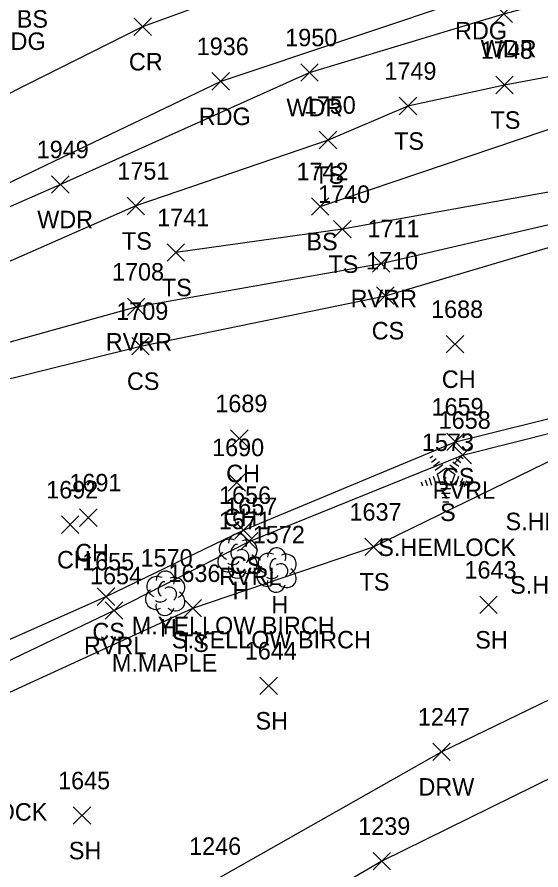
# Model space of a CAD drawing. Extents: x 1621633 to 1624015, y 417863 to 420979.
# Drawn here: x 1621766.2 to 1621826, y 417953.8 to 418051.2 of the extents above; entities that cross this region are included whole.
import ezdxf

# ---------------------------------------------------------------- set-up
doc = ezdxf.new("R2010")
doc.units = 0
for name, color, linetype in [('L_A', 7, 'Continuous'), ('L_C', 7, 'Continuous'), ('L_I', 7, 'Continuous'), ('L_TIC', 7, 'Continuous'), ('LAWA', 7, 'Continuous'), ('LAWE', 7, 'Continuous'), ('LELB', 7, 'Continuous'), ('LTC', 7, 'Continuous'), ('LTD', 7, 'Continuous'), ('P_A', 7, 'Continuous'), ('P_I', 7, 'Continuous'), ('P_TIC', 7, 'Continuous'), ('PEU', 7, 'Continuous'), ('PRC', 7, 'Continuous'), ('R_A', 7, 'Continuous'), ('R_I', 7, 'Continuous'), ('R_TIC', 7, 'Continuous'), ('RDW', 7, 'Continuous')]:
    doc.layers.add(name, color=color, linetype=linetype)

msp = doc.modelspace()

# ---------------------------------------------------------------- linework, layer by layer
at = {"layer": 'L_TIC'}
for points in [[(1621820.796, 418050.595), (1621822.796, 418052.595)], [(1621822.796, 418050.595), (1621820.796, 418052.595)], [(1621798.594, 418043.877), (1621800.594, 418045.877)], [(1621800.594, 418043.877), (1621798.594, 418045.877)], [(1621820.87, 418042.443), (1621822.87, 418044.443)], [(1621822.87, 418042.443), (1621820.87, 418044.443)], [(1621809.848, 418040.046), (1621811.848, 418042.046)], [(1621811.848, 418040.046), (1621809.848, 418042.046)], [(1621800.708, 418036.161), (1621802.708, 418038.161)], [(1621802.708, 418036.161), (1621800.708, 418038.161)], [(1621770.105, 418031.081), (1621772.105, 418033.081)], [(1621772.105, 418031.081), (1621770.105, 418033.081)], [(1621778.745, 418028.631), (1621780.745, 418030.631)], [(1621780.745, 418028.631), (1621778.745, 418030.631)], [(1621799.802, 418028.566), (1621801.802, 418030.566)], [(1621801.802, 418028.566), (1621799.802, 418030.566)], [(1621802.346, 418025.98), (1621804.346, 418027.98)], [(1621804.346, 418025.98), (1621802.346, 418027.98)], [(1621783.312, 418023.309), (1621785.312, 418025.309)], [(1621785.312, 418023.309), (1621783.312, 418025.309)], [(1621806.782, 418022.044), (1621808.782, 418024.044)], [(1621808.782, 418022.044), (1621806.782, 418024.044)], [(1621807.258, 418018.376), (1621809.258, 418020.376)], [(1621809.258, 418018.376), (1621807.258, 418020.376)], [(1621778.786, 418017.1), (1621780.786, 418019.1)], [(1621780.786, 418017.1), (1621778.786, 418019.1)], [(1621779.28, 418012.608), (1621781.28, 418014.608)], [(1621781.28, 418012.608), (1621779.28, 418014.608)], [(1621815.223, 418012.832), (1621817.223, 418014.832)], [(1621817.223, 418012.832), (1621815.223, 418014.832)], [(1621790.571, 418002.06), (1621792.571, 418004.06)], [(1621792.571, 418002.06), (1621790.571, 418004.06)], [(1621815.284, 418001.68), (1621817.284, 418003.68)], [(1621817.284, 418001.68), (1621815.284, 418003.68)], [(1621816.095, 418000.163), (1621818.095, 418002.163)], [(1621818.095, 418000.163), (1621816.095, 418002.163)], [(1621790.283, 417997.037), (1621792.283, 417999.037)], [(1621792.283, 417997.037), (1621790.283, 417999.037)], [(1621773.311, 417993.012), (1621775.311, 417995.012)], [(1621775.311, 417993.012), (1621773.311, 417995.012)], [(1621771.238, 417992.206), (1621773.238, 417994.206)], [(1621773.238, 417992.206), (1621771.238, 417994.206)], [(1621791.046, 417991.579), (1621793.046, 417993.579)], [(1621793.046, 417991.579), (1621791.046, 417993.579)], [(1621791.696, 417990.301), (1621793.696, 417992.301)], [(1621793.696, 417990.301), (1621791.696, 417992.301)], [(1621805.904, 417989.669), (1621807.904, 417991.669)], [(1621807.904, 417989.669), (1621805.904, 417991.669)], [(1621775.332, 417983.988), (1621777.332, 417985.988)], [(1621777.332, 417983.988), (1621775.332, 417985.988)], [(1621819.048, 417983.049), (1621821.048, 417985.049)], [(1621821.048, 417983.049), (1621819.048, 417985.049)], [(1621776.237, 417982.398), (1621778.237, 417984.398)], [(1621778.237, 417982.398), (1621776.237, 417984.398)], [(1621785.253, 417982.66), (1621787.253, 417984.66)], [(1621787.253, 417982.66), (1621785.253, 417984.66)], [(1621793.931, 417973.797), (1621795.931, 417975.797)], [(1621795.931, 417973.797), (1621793.931, 417975.797)], [(1621772.591, 417958.968), (1621774.591, 417960.968)], [(1621774.591, 417958.968), (1621772.591, 417960.968)]]:
    msp.add_lwpolyline(points, dxfattribs=at)
at = {"layer": 'LAWA'}
msp.add_lwpolyline([(1621679.191, 417971.595), (1621702.483, 417990.446), (1621715.012, 418000.477), (1621736.638, 418013.959), (1621752.876, 418023.199), (1621756.92, 418025.879), (1621771.105, 418032.081), (1621799.594, 418044.877), (1621821.796, 418051.595), (1621846.965, 418058.282), (1621864.113, 418063.689), (1621891.562, 418069.816), (1621913.254, 418074.106), (1621937.152, 418070.696)], dxfattribs=at)
at = {"layer": 'LAWE'}
for points in [[(1621694.469, 417944.857), (1621713.846, 417956.733), (1621742.172, 417966.049), (1621760.532, 417975.456), (1621777.237, 417983.398), (1621792.696, 417991.301), (1621817.095, 418001.163), (1621844.467, 418008.037), (1621871.363, 418013.308), (1621897.422, 418019.495), (1621922.912, 418028.804), (1621945.859, 418038.978), (1621969.359, 418051.535), (1621990.012, 418069.674), (1621996.064, 418084.217), (1621996.533, 418092.287)], [(1621682.822, 417967.998), (1621698.064, 417979.126), (1621716.448, 417990.621), (1621740.687, 418004.296), (1621760.276, 418012.676), (1621779.786, 418018.1), (1621807.782, 418023.044), (1621832.841, 418028.899), (1621852.452, 418034.783), (1621876.37, 418040.125), (1621904.646, 418043.594), (1621931.259, 418052.925), (1621950.617, 418064.927), (1621964.804, 418074.349), (1621971.864, 418081.724)]]:
    msp.add_lwpolyline(points, dxfattribs=at)
at = {"layer": 'LELB'}
for points in [[(1621694.018, 417945.604), (1621713.058, 417958.392), (1621741.418, 417968.002), (1621759.92, 417977.729), (1621776.332, 417984.988), (1621792.046, 417992.579), (1621816.284, 418002.68), (1621844.088, 418009.589), (1621869.849, 418015.692), (1621896.837, 418021.913), (1621921.805, 418030.632), (1621944.897, 418041.057), (1621968.773, 418053.066), (1621989.111, 418070.538), (1621994.262, 418084.512), (1621994.522, 418092.07)], [(1621714.218, 417979.319), (1621742.211, 418002.577), (1621762.579, 418009.214), (1621780.28, 418013.608), (1621808.258, 418019.376), (1621833.473, 418026.83), (1621853.516, 418030.646), (1621878.098, 418035.973), (1621904.446, 418042.094), (1621933.372, 418049.997), (1621951.553, 418063.416), (1621967.003, 418072.955), (1621972.682, 418081.713), (1621977.304, 418089.793)], [(1621962.893, 418084.645), (1621941.499, 418069.284), (1621934.526, 418059.292), (1621911.153, 418049.766), (1621884.836, 418045.66), (1621868.891, 418041.418), (1621850.259, 418038.198), (1621830.712, 418031.899), (1621803.346, 418026.98), (1621784.312, 418024.309)], [(1621870.082, 418049.389), (1621847.864, 418048.319), (1621821.87, 418043.443), (1621810.848, 418041.046), (1621801.708, 418037.161), (1621779.745, 418029.631), (1621758.68, 418020.378), (1621745.692, 418010.927), (1621727.629, 418000.827), (1621708.748, 417989.428), (1621682.341, 417970.694)], [(1621800.802, 418029.566), (1621829.213, 418039.175), (1621852.352, 418044.721), (1621867.236, 418045.074)], [(1621696.619, 417939.068), (1621723.715, 417952.351), (1621743.664, 417962.858), (1621762.067, 417972.573), (1621786.253, 417983.66), (1621806.904, 417990.669), (1621831.079, 418002.462), (1621857.774, 418009.445), (1621874.764, 418010.395)]]:
    msp.add_lwpolyline(points, dxfattribs=at)
at = {"layer": 'LTC'}
for p, q in [((1621813.327, 418000.831), (1621813.682, 418001.089)), ((1621813.537, 418000.366), (1621814.066, 418000.75)), ((1621816.354, 418000.723), (1621816.904, 418000.324)), ((1621816.725, 418001.072), (1621817.145, 418000.767)), ((1621813.746, 417999.9), (1621814.45, 418000.411)), ((1621813.956, 417999.434), (1621814.834, 418000.072)), ((1621814.18, 417998.979), (1621815.192, 417999.714)), ((1621815.192, 417999.714), (1621816.189, 417998.989)), ((1621815.612, 418000.027), (1621816.422, 417999.438)), ((1621815.983, 418000.375), (1621816.662, 417999.881)), ((1621813.27, 417998.544), (1621813.542, 417997.708)), ((1621813.726, 417998.76), (1621814.057, 417997.741)), ((1621814.18, 417998.979), (1621814.567, 417997.786)), ((1621816.189, 417998.989), (1621815.798, 417997.786)), ((1621816.627, 417998.718), (1621816.289, 417997.678)), ((1621812.36, 417998.11), (1621812.512, 417997.642)), ((1621812.815, 417998.327), (1621813.027, 417997.675)), ((1621815.798, 417997.786), (1621814.567, 417997.786)), ((1621817.071, 417998.467), (1621816.784, 417997.583)), ((1621817.516, 417998.217), (1621817.279, 417997.488)), ((1621817.96, 417997.967), (1621817.773, 417997.393)), ((1621815.76, 417997.286), (1621814.615, 417997.286)), ((1621815.676, 417996.786), (1621814.687, 417996.786)), ((1621815.592, 417996.286), (1621814.76, 417996.286)), ((1621815.508, 417995.786), (1621814.833, 417995.786))]:
    msp.add_line(p, q, dxfattribs=at)
at = {"layer": 'LTD'}
for p, q in [((1621791.344, 417989.688), (1621791.344, 417989.688)), ((1621791.344, 417989.688), (1621791.344, 417989.688)), ((1621795.799, 417988.071), (1621795.799, 417988.071)), ((1621795.799, 417988.071), (1621795.799, 417988.071)), ((1621783.065, 417985.418), (1621783.065, 417985.418)), ((1621783.065, 417985.418), (1621783.065, 417985.418))]:
    msp.add_line(p, q, dxfattribs=at)
for centre in [(1621791.391, 417991.122), (1621795.845, 417989.505), (1621783.112, 417986.852)]:
    msp.add_arc(centre, 1.047, 335.52715, 180.95627, dxfattribs=at)
for centre, major_axis, ratio, start_param, end_param in [((1621790.552, 417990.355), (1.21, -0.512), 0.895232, 1.570796, 4.712389), ((1621791.136, 417990.147), (-0.208, -0.792), 0.645439, 3.141593, 6.283185), ((1621792.386, 417990.272), (-1.141, -0.483), 0.949671, 1.570796, 4.712389), ((1621790.261, 417988.98), (0.584, -1.042), 0.959034, 3.141593, 6.283185), ((1621791.844, 417989.522), (-0.5, 0.667), 0.989748, 3.141593, 6.283185), ((1621792.344, 417988.855), (-1.09, 0.792), 0.841452, 1.570796, 4.712389), ((1621795.007, 417988.738), (1.21, -0.512), 0.895232, 1.570796, 4.712389), ((1621796.84, 417988.655), (-1.141, -0.483), 0.949671, 1.570796, 4.712389), ((1621790.886, 417988.938), (-0.625, -0.083), 0.423636, 0, 3.141593), ((1621795.59, 417988.529), (-0.208, -0.792), 0.645439, 3.141593, 6.283185), ((1621796.299, 417987.905), (-0.5, 0.667), 0.989748, 3.141593, 6.283185), ((1621791.344, 417988.188), (0.265, 1.061), 0.942809, 1.570796, 4.712389), ((1621794.715, 417987.363), (0.584, -1.042), 0.959034, 3.141593, 6.283185), ((1621796.799, 417987.238), (-1.09, 0.792), 0.841452, 1.570796, 4.712389), ((1621782.273, 417986.085), (1.21, -0.512), 0.895232, 1.570796, 4.712389), ((1621784.106, 417986.002), (-1.141, -0.483), 0.949671, 1.570796, 4.712389), ((1621795.799, 417986.571), (0.265, 1.061), 0.942809, 1.570796, 4.712389), ((1621795.34, 417987.321), (-0.625, -0.083), 0.423636, 0, 3.141593), ((1621782.856, 417985.876), (-0.208, -0.792), 0.645439, 3.141593, 6.283185), ((1621783.565, 417985.251), (-0.5, 0.667), 0.989748, 3.141593, 6.283185), ((1621781.982, 417984.709), (0.584, -1.042), 0.959034, 3.141593, 6.283185), ((1621784.065, 417984.585), (-1.09, 0.792), 0.841452, 1.570796, 4.712389), ((1621783.065, 417983.918), (0.265, 1.061), 0.942809, 1.570796, 4.712389), ((1621782.607, 417984.668), (-0.625, -0.083), 0.423636, 0, 3.141593)]:
    msp.add_ellipse(centre, major_axis=major_axis, ratio=ratio, start_param=start_param, end_param=end_param, dxfattribs=at)
at = {"layer": 'P_TIC'}
for points in [[(1621779.514, 418049.109), (1621781.514, 418051.109)], [(1621781.514, 418049.109), (1621779.514, 418051.109)], [(1621788.443, 418042.868), (1621790.443, 418044.868)], [(1621790.443, 418042.868), (1621788.443, 418044.868)]]:
    msp.add_lwpolyline(points, dxfattribs=at)
at = {"layer": 'PEU'}
msp.add_lwpolyline([(1621912.204, 418078.592), (1621880.997, 418070.288), (1621848.822, 418062.508), (1621818.735, 418053.659), (1621789.443, 418043.868), (1621760.318, 418029.904), (1621735.432, 418015.464), (1621709.615, 417999.398), (1621686.1, 417982.194), (1621676.517, 417973.897)], dxfattribs=at)
at = {"layer": 'PRC'}
msp.add_lwpolyline([(1621971.067, 418099.341), (1621938.438, 418093.726), (1621906.629, 418086.952), (1621874.869, 418079.941), (1621842.519, 418071.194), (1621811.531, 418061.42), (1621780.514, 418050.109), (1621750.947, 418035.3), (1621723.041, 418018.53), (1621696.18, 418000.53), (1621670.933, 417981.571)], dxfattribs=at)
at = {"layer": 'R_TIC'}
for points in [[(1621813.671, 417966.246), (1621815.671, 417968.246)], [(1621815.671, 417966.246), (1621813.671, 417968.246)], [(1621806.862, 417953.759), (1621808.862, 417955.759)], [(1621808.862, 417953.759), (1621806.862, 417955.759)]]:
    msp.add_lwpolyline(points, dxfattribs=at)
at = {"layer": 'RDW'}
msp.add_lwpolyline([(1621894.363, 417990.232), (1621865.95, 417979.751), (1621835.24, 417968.23), (1621807.862, 417954.759), (1621779.016, 417937.89), (1621749.255, 417923.342), (1621721.772, 417904.02), (1621715.875, 417914.033), (1621734.513, 417925.445), (1621760.095, 417937.756), (1621788.575, 417952.475), (1621814.671, 417967.246), (1621841.022, 417980.019), (1621869.66, 417990.005), (1621898.189, 417999.842)], dxfattribs=at)

# ---------------------------------------------------------------- texts
at = {"layer": 'L_A'}
for s, p in [('BS', (1621766.131, 418050.001)), ('WDR', (1621819.158, 418046.595)), ('WDR', (1621796.956, 418039.877)), ('TS', (1621820.28, 418038.443)), ('TS', (1621809.257, 418036.046)), ('TS', (1621800.118, 418032.161)), ('WDR', (1621768.467, 418027.081)), ('TS', (1621778.154, 418024.631)), ('BS', (1621799.243, 418024.566)), ('TS', (1621801.756, 418021.98)), ('TS', (1621782.722, 418019.309)), ('RVRR', (1621804.294, 418018.044)), ('CS', (1621806.699, 418014.376)), ('RVRR', (1621776.298, 418013.1)), ('CS', (1621778.721, 418008.608)), ('CH', (1621814.712, 418008.832)), ('CH', (1621790.06, 417998.06)), ('CS', (1621814.725, 417997.68)), ('RVRL', (1621813.662, 417996.163)), ('S', (1621814.518, 417993.623)), ('CH', (1621789.771, 417993.037)), ('CH', (1621772.799, 417989.012)), ('CH', (1621770.726, 417988.206)), ('CS', (1621790.486, 417987.579)), ('RVRL', (1621789.263, 417986.301)), ('TS', (1621805.313, 417985.669)), ('H', (1621790.777, 417984.688)), ('H', (1621795.232, 417983.071)), ('CS', (1621774.773, 417979.988)), ('H', (1621782.498, 417980.418)), ('SH', (1621818.536, 417979.049)), ('RVRL', (1621773.804, 417978.398)), ('TS', (1621784.662, 417978.66)), ('SH', (1621793.419, 417969.797)), ('SH', (1621772.079, 417954.968))]:
    msp.add_text(s, height=2, dxfattribs=at).set_placement(p)
at = {"layer": 'L_C'}
for s, p in [('S.HEMLOCK', (1621821.997, 417992.575)), ('S.HEMLOCK', (1621807.447, 417989.623)), ('S.HEMLOCK', (1621822.529, 417985.323)), ('M.YELLOW BIRCH', (1621779.281, 417980.688)), ('S.YELLOW BIRCH', (1621783.862, 417979.071)), ('M.MAPLE', (1621777.002, 417976.418)), ('S.HEMLOCK', (1621753.872, 417959.388))]:
    msp.add_text(s, height=2, dxfattribs=at).set_placement(p)
at = {"layer": 'L_I'}
for s, p in [('1950', (1621796.815, 418047.877)), ('1748', (1621819.177, 418046.443)), ('1749', (1621808.147, 418044.046)), ('1750', (1621798.929, 418040.161)), ('1949', (1621768.404, 418035.081)), ('1751', (1621777.619, 418032.631)), ('1742', (1621798.109, 418032.566)), ('1740', (1621800.567, 418029.98)), ('1741', (1621782.186, 418027.309)), ('1711', (1621806.223, 418026.044)), ('1710', (1621806.046, 418022.376)), ('1708', (1621777.015, 418021.1)), ('1709', (1621777.501, 418016.608)), ('1688', (1621813.483, 418016.832)), ('1689', (1621788.823, 418006.06)), ('1659', (1621813.536, 418005.68)), ('1658', (1621814.355, 418004.163)), ('1573', (1621812.439, 418001.623)), ('1690', (1621788.456, 418001.037)), ('1691', (1621772.138, 417997.012)), ('1692', (1621769.498, 417996.206)), ('1656', (1621789.25, 417995.579)), ('1657', (1621789.956, 417994.301)), ('1637', (1621804.164, 417993.669)), ('1571', (1621789.218, 417992.688)), ('1572', (1621793.106, 417991.071)), ('1655', (1621773.592, 417987.988)), ('1570', (1621780.285, 417988.418)), ('1643', (1621817.308, 417987.049)), ('1654', (1621774.497, 417986.398)), ('1636', (1621783.458, 417986.66)), ('1644', (1621792.191, 417977.797)), ('1645', (1621770.851, 417962.968))]:
    msp.add_text(s, height=2, dxfattribs=at).set_placement(p)
at = {"layer": 'LTC'}
msp.add_text('.', height=1.037, rotation=270, dxfattribs=at).set_placement((1621815.075, 417998.727))
at = {"layer": 'P_A'}
for s, p in [('RDG', (1621816.223, 418048.659)), ('RDG', (1621763.488, 418047.456)), ('CR', (1621778.947, 418045.109)), ('RDG', (1621786.932, 418038.868))]:
    msp.add_text(s, height=2, dxfattribs=at).set_placement(p)
at = {"layer": 'P_I'}
msp.add_text('1936', height=2, dxfattribs=at).set_placement((1621786.695, 418046.868))
at = {"layer": 'R_A'}
msp.add_text('DRW', height=2, dxfattribs=at).set_placement((1621812.041, 417962.246))
at = {"layer": 'R_I'}
for s, p in [('1247', (1621811.978, 417970.246)), ('1239', (1621805.161, 417957.759)), ('1246', (1621785.827, 417955.475))]:
    msp.add_text(s, height=2, dxfattribs=at).set_placement(p)

doc.saveas('drawing.dxf')
